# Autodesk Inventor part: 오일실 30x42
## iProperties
IsCustomPart: 0
Company: 한국ATC센터
Created: 2009-02
Part Number: 오일실 30x42
Material: 고무
Description: 오일-실
Document SubType Name: Modeling
Standard: KS B 2804
Designer: KYOUNG IL JANG
Standards Organization: KS
Language: ko-KR
Size Designation: S - 30 42 8
Categories: <MemberInstance><Categories><Category DisplayName="샤프트 부품" InternalName="7f7aeb1f-a693-4053-b835-cee3144e0d98" Mnemonic="SHFT"><Category DisplayName="실링" Intern
Density: 0.93 g/cm^3
Author: KYOUNG IL JANG
